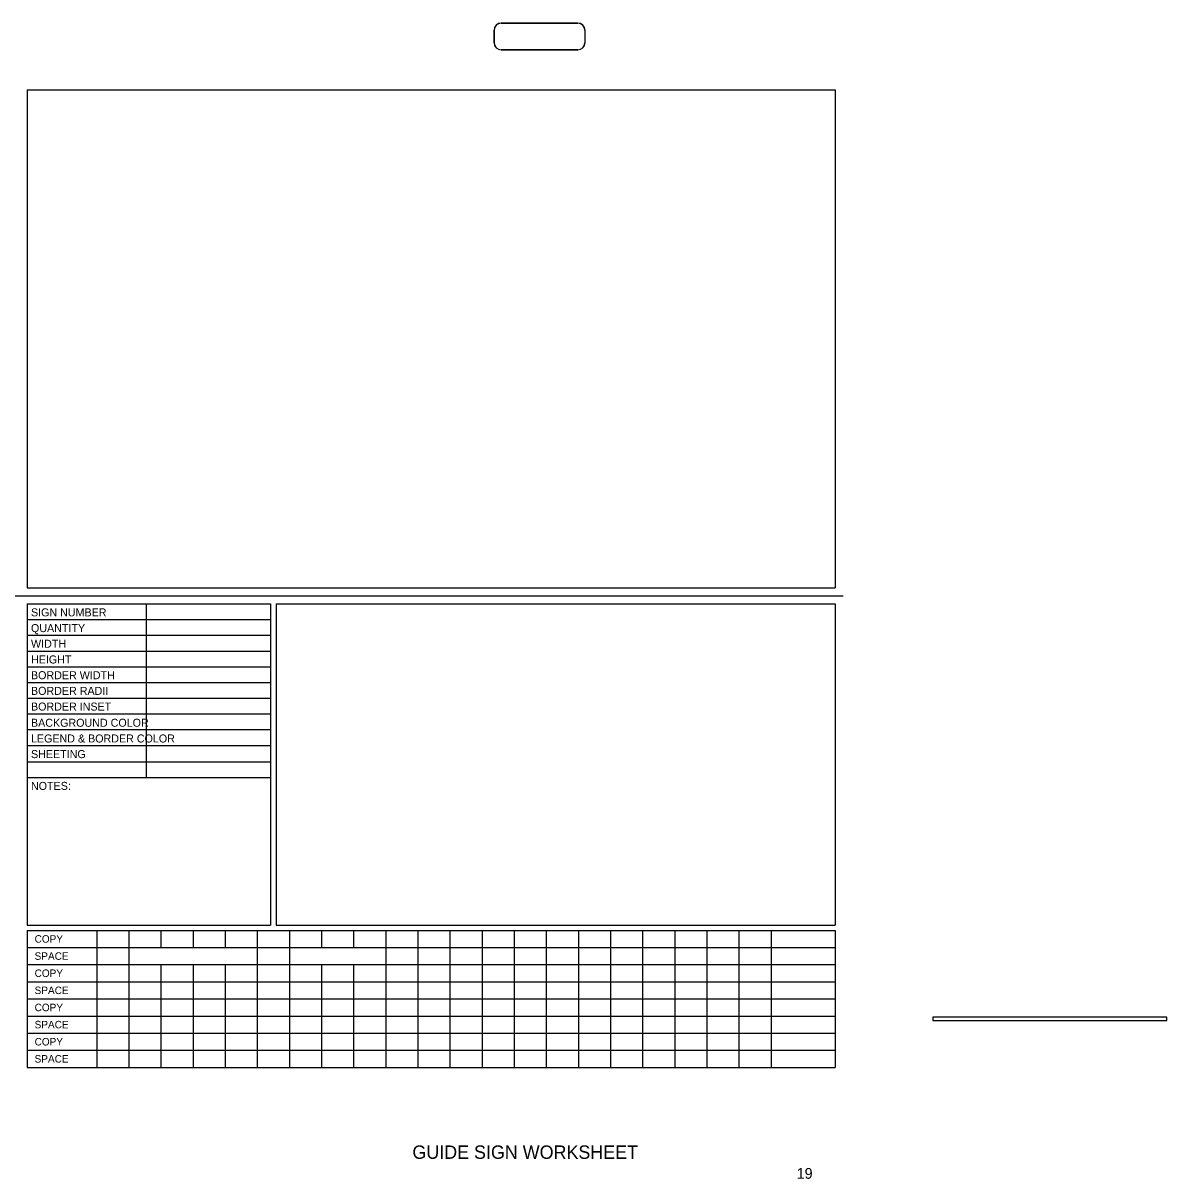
# Model space of a CAD drawing. Extents: x 10268197 to 10268511, y 2141503 to 2142677.
# Drawn here: x 10268395.1 to 10268502, y 2142267.8 to 2142375.8 of the extents above; entities that cross this region are included whole.
import ezdxf

# ---------------------------------------------------------------- set-up
doc = ezdxf.new("R2010")
doc.units = 0
for name, color, linetype in [('GSColorFill', 7, 'Continuous'), ('GSOutline', 7, 'Continuous'), ('SheetBorder_dp', 7, 'Continuous'), ('SumBoxLines_dp', 7, 'Continuous'), ('SumBoxLinesMin_dp', 7, 'Continuous'), ('TextMisc', 7, 'Continuous'), ('TextShtNo', 7, 'Continuous')]:
    doc.layers.add(name, color=color, linetype=linetype)

msp = doc.modelspace()

# ---------------------------------------------------------------- linework, layer by layer
at = {"layer": 'GSColorFill'}
for p, q in [((10268446.93, 2142375.77), (10268439.77, 2142375.77)), ((10268446.93, 2142375.77), (10268439.77, 2142375.77)), ((10268439.77, 2142375.76), (10268446.93, 2142375.76)), ((10268439.1, 2142375.11), (10268439.1, 2142373.94)), ((10268439.1, 2142375.11), (10268439.1, 2142373.94)), ((10268439.12, 2142373.94), (10268439.12, 2142375.11)), ((10268447.58, 2142375.11), (10268447.58, 2142373.94)), ((10268447.6, 2142373.94), (10268447.6, 2142375.11)), ((10268447.6, 2142373.94), (10268447.6, 2142375.11)), ((10268439.77, 2142373.27), (10268439.77, 2142373.29)), ((10268446.93, 2142373.29), (10268439.77, 2142373.29)), ((10268439.77, 2142373.29), (10268439.77, 2142373.27)), ((10268439.77, 2142373.27), (10268446.93, 2142373.27)), ((10268439.77, 2142373.27), (10268446.93, 2142373.27))]:
    msp.add_line(p, q, dxfattribs=at)
for centre, radius, start, end in [((10268439.77, 2142375.11), 0.667, 90, 180), ((10268439.77, 2142375.11), 0.667, 90, 180), ((10268439.77, 2142375.11), 0.65, 90, 180), ((10268446.93, 2142375.11), 0.667, 0, 90), ((10268446.93, 2142375.11), 0.667, 0, 90), ((10268446.93, 2142375.11), 0.65, 0, 90), ((10268439.77, 2142373.94), 0.667, 180, 270), ((10268439.77, 2142373.94), 0.667, 180, 270), ((10268439.77, 2142373.94), 0.65, 180, 270), ((10268446.93, 2142373.94), 0.667, 270, 0), ((10268446.93, 2142373.94), 0.65, 270, 0), ((10268446.93, 2142373.94), 0.667, 270, 0)]:
    msp.add_arc(centre, radius, start, end, dxfattribs=at)
at = {"layer": 'GSOutline'}
for p, q in [((10268480.08, 2142282.92), (10268480.08, 2142282.61)), ((10268501.96, 2142282.92), (10268480.08, 2142282.92)), ((10268480.08, 2142282.61), (10268501.96, 2142282.61)), ((10268501.96, 2142282.61), (10268501.96, 2142282.92))]:
    msp.add_line(p, q, dxfattribs=at)
at = {"layer": 'SheetBorder_dp'}
msp.add_line((10268317.73, 2142322.28), (10268471.73, 2142322.28), dxfattribs=at)
at = {"layer": 'SumBoxLines_dp'}
for p, q in [((10268395.48, 2142369.53), (10268470.98, 2142369.53)), ((10268395.48, 2142369.53), (10268395.48, 2142323.03)), ((10268470.98, 2142369.53), (10268470.98, 2142323.03)), ((10268395.48, 2142323.03), (10268470.98, 2142323.03)), ((10268395.48, 2142321.53), (10268395.48, 2142291.53)), ((10268395.48, 2142321.53), (10268418.23, 2142321.53)), ((10268406.6, 2142321.53), (10268406.6, 2142305.31)), ((10268418.23, 2142321.53), (10268418.23, 2142291.53)), ((10268418.73, 2142321.53), (10268418.73, 2142291.53)), ((10268418.73, 2142321.53), (10268470.98, 2142321.53)), ((10268470.98, 2142321.53), (10268470.98, 2142291.53)), ((10268395.48, 2142320.07), (10268418.23, 2142320.07)), ((10268395.48, 2142318.59), (10268418.23, 2142318.59)), ((10268395.48, 2142317.12), (10268418.23, 2142317.12)), ((10268395.48, 2142315.66), (10268418.23, 2142315.66)), ((10268395.48, 2142314.19), (10268418.23, 2142314.19)), ((10268395.48, 2142312.73), (10268418.23, 2142312.73)), ((10268395.48, 2142311.26), (10268418.23, 2142311.26)), ((10268395.48, 2142309.78), (10268418.23, 2142309.78)), ((10268395.48, 2142308.31), (10268418.23, 2142308.31)), ((10268395.48, 2142306.78), (10268418.23, 2142306.78)), ((10268395.48, 2142305.31), (10268418.23, 2142305.31)), ((10268395.48, 2142291.53), (10268418.23, 2142291.53)), ((10268395.48, 2142291.03), (10268470.98, 2142291.03)), ((10268395.48, 2142291.03), (10268395.48, 2142278.23)), ((10268401.98, 2142291.03), (10268401.98, 2142278.23)), ((10268404.98, 2142291.03), (10268404.98, 2142278.23)), ((10268407.98, 2142291.03), (10268407.98, 2142289.43)), ((10268410.98, 2142291.03), (10268410.98, 2142289.43)), ((10268413.98, 2142291.03), (10268413.98, 2142289.43)), ((10268416.98, 2142291.03), (10268416.98, 2142287.83)), ((10268418.73, 2142291.53), (10268470.98, 2142291.53)), ((10268419.98, 2142291.03), (10268419.98, 2142289.43)), ((10268422.98, 2142291.03), (10268422.98, 2142289.43)), ((10268425.98, 2142291.03), (10268425.98, 2142289.43)), ((10268428.98, 2142291.03), (10268428.98, 2142287.83)), ((10268431.98, 2142291.03), (10268431.98, 2142287.83)), ((10268434.98, 2142291.03), (10268434.98, 2142289.43)), ((10268437.98, 2142291.03), (10268437.98, 2142289.43)), ((10268440.98, 2142291.03), (10268440.98, 2142287.83)), ((10268443.98, 2142291.03), (10268443.98, 2142287.83)), ((10268446.98, 2142291.03), (10268446.98, 2142289.43)), ((10268449.98, 2142291.03), (10268449.98, 2142289.43)), ((10268452.98, 2142291.03), (10268452.98, 2142289.43)), ((10268455.98, 2142291.03), (10268455.98, 2142289.43)), ((10268458.98, 2142291.03), (10268458.98, 2142289.43)), ((10268461.98, 2142291.03), (10268461.98, 2142289.43)), ((10268464.98, 2142291.03), (10268464.98, 2142289.43)), ((10268470.98, 2142291.03), (10268470.98, 2142278.23)), ((10268419.98, 2142289.43), (10268419.98, 2142284.63)), ((10268434.98, 2142289.43), (10268434.98, 2142283.03)), ((10268437.98, 2142289.43), (10268437.98, 2142281.43)), ((10268440.98, 2142289.43), (10268440.98, 2142281.43)), ((10268443.98, 2142289.43), (10268443.98, 2142283.03)), ((10268446.98, 2142289.43), (10268446.98, 2142283.03)), ((10268449.98, 2142289.43), (10268449.98, 2142278.23)), ((10268452.98, 2142289.43), (10268452.98, 2142278.23)), ((10268455.98, 2142289.43), (10268455.98, 2142283.03)), ((10268458.98, 2142289.43), (10268458.98, 2142283.03)), ((10268461.98, 2142289.43), (10268461.98, 2142283.03)), ((10268464.98, 2142289.43), (10268464.98, 2142278.23)), ((10268395.48, 2142287.83), (10268470.98, 2142287.83)), ((10268407.98, 2142287.83), (10268407.98, 2142281.43)), ((10268410.98, 2142287.83), (10268410.98, 2142281.43)), ((10268413.98, 2142287.83), (10268413.98, 2142281.43)), ((10268416.98, 2142287.83), (10268416.98, 2142284.63)), ((10268422.98, 2142287.83), (10268422.98, 2142284.63)), ((10268425.98, 2142287.83), (10268425.98, 2142284.63)), ((10268428.98, 2142287.83), (10268428.98, 2142284.63)), ((10268431.98, 2142287.83), (10268431.98, 2142283.03)), ((10268395.48, 2142284.63), (10268470.98, 2142284.63)), ((10268416.98, 2142284.63), (10268416.98, 2142281.43)), ((10268419.98, 2142284.63), (10268419.98, 2142281.43)), ((10268422.98, 2142284.63), (10268422.98, 2142281.43)), ((10268425.98, 2142284.63), (10268425.98, 2142281.43)), ((10268428.98, 2142284.63), (10268428.98, 2142281.43)), ((10268431.98, 2142283.03), (10268431.98, 2142278.23)), ((10268434.98, 2142283.03), (10268434.98, 2142278.23)), ((10268443.98, 2142283.03), (10268443.98, 2142278.23)), ((10268446.98, 2142283.03), (10268446.98, 2142278.23)), ((10268455.98, 2142283.03), (10268455.98, 2142278.23)), ((10268458.98, 2142283.03), (10268458.98, 2142278.23)), ((10268461.98, 2142283.03), (10268461.98, 2142278.23)), ((10268395.48, 2142281.43), (10268470.98, 2142281.43)), ((10268407.98, 2142281.43), (10268407.98, 2142278.23)), ((10268410.98, 2142281.43), (10268410.98, 2142278.23)), ((10268413.98, 2142281.43), (10268413.98, 2142278.23)), ((10268416.98, 2142281.43), (10268416.98, 2142278.23)), ((10268419.98, 2142281.43), (10268419.98, 2142278.23)), ((10268422.98, 2142281.43), (10268422.98, 2142278.23)), ((10268425.98, 2142281.43), (10268425.98, 2142278.23)), ((10268428.98, 2142281.43), (10268428.98, 2142278.23)), ((10268437.98, 2142281.43), (10268437.98, 2142278.23)), ((10268440.98, 2142281.43), (10268440.98, 2142278.23)), ((10268395.48, 2142278.23), (10268470.98, 2142278.23))]:
    msp.add_line(p, q, dxfattribs=at)
at = {"layer": 'SumBoxLinesMin_dp'}
for p, q in [((10268395.48, 2142289.43), (10268470.98, 2142289.43)), ((10268395.48, 2142286.23), (10268470.98, 2142286.23)), ((10268395.48, 2142283.03), (10268470.98, 2142283.03)), ((10268395.48, 2142279.83), (10268470.98, 2142279.83))]:
    msp.add_line(p, q, dxfattribs=at)

# ---------------------------------------------------------------- texts
at = {"layer": 'TextMisc'}
for s, height, p in [('SIGN NUMBER', 0.7476, (10268395.84, 2142320.36)), ('QUANTITY', 0.748, (10268395.84, 2142318.89)), ('WIDTH', 0.748, (10268395.84, 2142317.43)), ('HEIGHT', 0.748, (10268395.84, 2142315.96)), ('BORDER WIDTH', 0.7476, (10268395.84, 2142314.49)), ('BORDER RADII', 0.7476, (10268395.84, 2142313.03)), ('BORDER INSET', 0.7476, (10268395.84, 2142311.56)), ('BACKGROUND COLOR', 0.7476, (10268395.84, 2142310.05)), ('LEGEND & BORDER COLOR', 0.7476, (10268395.84, 2142308.58)), ('SHEETING', 0.748, (10268395.84, 2142307.12)), ('NOTES:', 0.748, (10268395.84, 2142304.15)), ('COPY', 0.7, (10268396.18, 2142289.88)), ('SPACE', 0.7, (10268396.18, 2142288.28)), ('COPY', 0.7, (10268396.18, 2142286.68)), ('SPACE', 0.7, (10268396.18, 2142285.08)), ('COPY', 0.7, (10268396.18, 2142283.48)), ('SPACE', 0.7, (10268396.18, 2142281.88)), ('COPY', 0.7, (10268396.18, 2142280.28)), ('SPACE', 0.7, (10268396.18, 2142278.68))]:
    msp.add_text(s, height=height, dxfattribs=at).set_placement(p)
msp.add_text('     GUIDE SIGN WORKSHEET      ', height=1.25, rotation=360, dxfattribs=at).set_placement((10268429.15, 2142269.69))
at = {"layer": 'TextShtNo'}
msp.add_text('19', height=1, rotation=360, dxfattribs=at).set_placement((10268467.37, 2142267.83))

doc.saveas('drawing.dxf')
